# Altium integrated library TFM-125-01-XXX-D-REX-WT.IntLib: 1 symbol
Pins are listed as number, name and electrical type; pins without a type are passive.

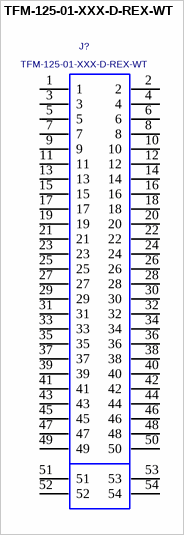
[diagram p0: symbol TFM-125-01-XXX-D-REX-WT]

## TFM-125-01-XXX-D-REX-WT
designator J?
Terminal Strip, Double Row, Right Angle, Weld tabs, 25 Positions Per Row.; MANUFACTURER: SAMTEC
footprint TFM-125-01-XXX-D-REX-WT
pins: 1, 2, 3, 4, 5, 6, 7, 8, 9, 10, 11, 12, 13, 14, 15, 16, 17, 18, 19, 20, 21, 22, 23, 24, 25, 26, 27, 28, 29, 30, 31, 32, 33, 34, 35, 36, 37, 38, 39, 40, 41, 42, 43, 44, 45, 46, 47, 48, 49, 50, 51, 52, 53, 54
